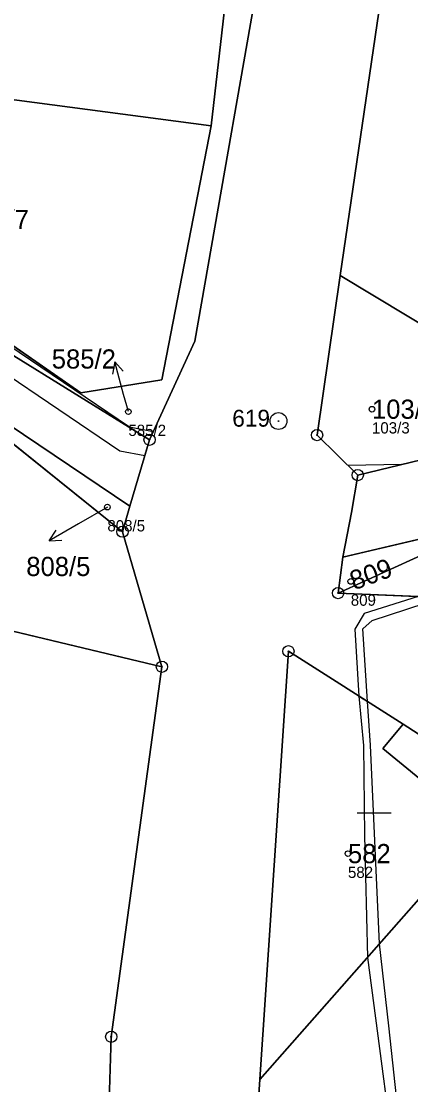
# Model space of a CAD drawing. Extents: x -734965 to -732523, y -1026217 to -1023680.
# Drawn here: x -734214.8 to -734180.3, y -1025552.4 to -1025458.1 of the extents above; entities that cross this region are included whole.
import ezdxf

# ---------------------------------------------------------------- set-up
doc = ezdxf.new("R2010")
doc.units = 0
for name, color, linetype in [('Vrstva 1', 7, 'Continuous'), ('Vrstva 13', 7, 'Continuous'), ('Vrstva 2', 7, 'Continuous'), ('Vrstva 3', 7, 'Continuous'), ('Vrstva 50', 7, 'Continuous'), ('Vrstva 51', 7, 'Continuous'), ('Vrstva 7', 7, 'Continuous'), ('Vrstva 8', 7, 'Continuous')]:
    doc.layers.add(name, color=color, linetype=linetype)

msp = doc.modelspace()

# ---------------------------------------------------------------- linework, layer by layer
at = {"layer": 'Vrstva 1'}
for p, q in [((-734196.71, -1025456.31), (-734198, -1025467.39)), ((-734209.55, -1025491.06), (-734254.45, -1025459.93)), ((-734254.45, -1025459.93), (-734198, -1025467.39)), ((-734198, -1025467.39), (-734202.38, -1025489.91)), ((-734165.69, -1025493.21), (-734186.54, -1025480.67)), ((-734205.86, -1025503.37), (-734226.72, -1025486.62)), ((-734226.72, -1025486.62), (-734205.2, -1025501.12)), ((-734202.38, -1025489.91), (-734209.55, -1025491.06)), ((-734203.46, -1025495.22), (-734205.2, -1025501.12)), ((-734205.2, -1025501.12), (-734205.86, -1025503.37)), ((-734172.72, -1025502.44), (-734186.74, -1025508.81)), ((-734172.72, -1025502.44), (-734186.32, -1025505.64)), ((-734202.36, -1025515.34), (-734205.86, -1025503.37)), ((-734186.74, -1025508.81), (-734186.32, -1025505.64)), ((-734235.25, -1025507.49), (-734202.36, -1025515.34)), ((-734176.27, -1025509.26), (-734186.74, -1025508.81)), ((-734180.96, -1025520.44), (-734179.64, -1025521.28)), ((-734174.08, -1025529.72), (-734193.69, -1025551.93)), ((-734195.13, -1025573.4), (-734193.69, -1025551.93))]:
    msp.add_line(p, q, dxfattribs=at)
for points in [[(-734186.54, -1025480.67), (-734181, -1025442.74), (-734169.15, -1025369.4), (-734156.59, -1025300)], [(-734195.46, -1025445.51), (-734192.73, -1025448.2), (-734199.45, -1025486.49), (-734203.46, -1025495.22)], [(-734263.8, -1025455.17), (-734222.99, -1025483.18), (-734203.46, -1025495.22)], [(-734186.54, -1025480.67), (-734188.6, -1025494.81), (-734184.99, -1025498.35)], [(-734184.99, -1025498.35), (-734166.17, -1025493.81), (-734165.12, -1025493.56)], [(-734186.32, -1025505.64), (-734185.56, -1025501.67), (-734184.99, -1025498.35)], [(-734193.69, -1025551.93), (-734191.14, -1025513.97), (-734180.96, -1025520.44)], [(-734202.36, -1025515.34), (-734206.86, -1025548.15), (-734208.37, -1025596.37), (-734208.2, -1025609.54), (-734207.24, -1025660.18), (-734210.4, -1025681.11), (-734230.12, -1025705.46), (-734245.49, -1025721.03)], [(-734180.96, -1025520.44), (-734182.76, -1025522.59), (-734174.08, -1025529.72)]]:
    msp.add_lwpolyline(points, dxfattribs=at)
at = {"layer": 'Vrstva 13'}
for points in [[(-734361.97, -1025583.56), (-734362.38, -1025583.9), (-734360.91, -1025585.58), (-734360.55, -1025585.27), (-734270.04, -1025510.33), (-734255.65, -1025499.06), (-734240.06, -1025486.22), (-734233.18, -1025477.89), (-734206.11, -1025496.21), (-734203.87, -1025496.63), (-734203.46, -1025495.22), (-734203.13, -1025494.51), (-734205.25, -1025494.11), (-734233.61, -1025474.92), (-734243.1, -1025486.41), (-734271.43, -1025508.6)], [(-734181.1, -1025497.41), (-734185.85, -1025497.51), (-734184.99, -1025498.35)], [(-734184.12, -1025518.43), (-734184.54, -1025511.99), (-734183.7, -1025511.25), (-734177.46, -1025509.21), (-734179.63, -1025509.12), (-734184.43, -1025510.63), (-734185.25, -1025512), (-734184.89, -1025517.94)], [(-734184.89, -1025517.94), (-734184.47, -1025522.34), (-734184.4, -1025530.29), (-734184.14, -1025541.11), (-734181.15, -1025563.75), (-734181.28, -1025567.46), (-734180.79, -1025570.32), (-734181.32, -1025574.41), (-734179.58, -1025577.99), (-734179.04, -1025577.73), (-734180.7, -1025574.31), (-734180.15, -1025570.52), (-734180.68, -1025567.42), (-734180.53, -1025563.04), (-734182.22, -1025547.18), (-734183.07, -1025539.91), (-734183.87, -1025522.3), (-734184.12, -1025518.43)]]:
    msp.add_lwpolyline(points, close=True, dxfattribs=at)
at = {"layer": 'Vrstva 3'}
msp.add_line((-734185.038, -1025528.3), (-734182.038, -1025528.3), dxfattribs=at)
at = {"layer": 'Vrstva 50'}
for centre in [(-734205.34, -1025492.73), (-734183.73, -1025492.51), (-734207.2, -1025501.19), (-734185.61, -1025507.78), (-734185.86, -1025531.91)]:
    msp.add_circle(centre, 0.25, dxfattribs=at)
at = {"layer": 'Vrstva 51'}
for points in [[(-734192.77, -1025655.13), (-734195.13, -1025573.4), (-734193.69, -1025551.93), (-734191.14, -1025513.97), (-734180.96, -1025520.44), (-734179.64, -1025521.28), (-734165.41, -1025504.9), (-734163.5, -1025502.7), (-734176.27, -1025509.26), (-734186.74, -1025508.81), (-734186.32, -1025505.64), (-734185.56, -1025501.67), (-734184.99, -1025498.35), (-734188.6, -1025494.81), (-734186.54, -1025480.67), (-734181, -1025442.74), (-734169.15, -1025369.4), (-734156.59, -1025300)], [(-734194.12, -1025358.97), (-734195.38, -1025379.43), (-734196.25, -1025388.44), (-734196.61, -1025399.41), (-734197.28, -1025419.42), (-734197.72, -1025429.14), (-734197.39, -1025432.52), (-734196.17, -1025444.81), (-734195.46, -1025445.51), (-734192.73, -1025448.2), (-734199.45, -1025486.49), (-734203.46, -1025495.22), (-734205.2, -1025501.12), (-734205.86, -1025503.37), (-734202.36, -1025515.34), (-734206.86, -1025548.15), (-734208.37, -1025596.37), (-734208.2, -1025609.54), (-734207.24, -1025660.18)], [(-734408.65, -1025376.56), (-734352.1, -1025403.23), (-734332.12, -1025413.11), (-734329.37, -1025414.87), (-734311.09, -1025424.35), (-734301.4, -1025430.8), (-734294.32, -1025437.04), (-734286.2, -1025442.28), (-734276.38, -1025449.51), (-734274.57, -1025450.96), (-734262.95, -1025459.45), (-734261.75, -1025460.33), (-734233.78, -1025481.1), (-734226.72, -1025486.62), (-734205.2, -1025501.12), (-734203.46, -1025495.22), (-734222.99, -1025483.18), (-734263.8, -1025455.17), (-734266.91, -1025452.06), (-734308.55, -1025423.43), (-734328.09, -1025410.59), (-734377.2, -1025388.12), (-734422.07, -1025368.4)], [(-734181, -1025442.74), (-734186.54, -1025480.67), (-734165.69, -1025493.21), (-734164.83, -1025492.89), (-734164.35, -1025493.02), (-734163.91, -1025492.8), (-734163.87, -1025492.31), (-734162.26, -1025491.06), (-734160.77, -1025489.7), (-734159.53, -1025488.12), (-734158.87, -1025486.23), (-734158.67, -1025484.23), (-734158.88, -1025482.22), (-734159.26, -1025480.77), (-734172.24, -1025442.54)], [(-734080.79, -1025492.01), (-734115.3, -1025489.58), (-734156.72, -1025495.18), (-734160.08, -1025496.7), (-734165.12, -1025493.56), (-734166.17, -1025493.81), (-734184.99, -1025498.35), (-734185.56, -1025501.67), (-734186.32, -1025505.64), (-734172.72, -1025502.44), (-734168.11, -1025501.36), (-734160.71, -1025499.62), (-734158.48, -1025499.09), (-734156.85, -1025498.71), (-734144.25, -1025495.75), (-734122.54, -1025492.68), (-734091.71, -1025493.39)]]:
    msp.add_lwpolyline(points, dxfattribs=at)
for points in [[(-734222.99, -1025483.18), (-734203.46, -1025495.22), (-734199.45, -1025486.49), (-734192.73, -1025448.2), (-734195.46, -1025445.51), (-734196.71, -1025456.31), (-734198, -1025467.39), (-734202.38, -1025489.91), (-734209.55, -1025491.06), (-734254.45, -1025459.93), (-734263.46, -1025453.25), (-734263.8, -1025455.17)], [(-734198, -1025467.39), (-734196.71, -1025456.31), (-734262.44, -1025447.52), (-734263.46, -1025453.25), (-734254.45, -1025459.93)], [(-734202.38, -1025489.91), (-734198, -1025467.39), (-734254.45, -1025459.93), (-734209.55, -1025491.06)], [(-734166.17, -1025493.81), (-734165.12, -1025493.56), (-734165.69, -1025493.21), (-734186.54, -1025480.67), (-734188.6, -1025494.81), (-734184.99, -1025498.35)], [(-734205.86, -1025503.37), (-734226.72, -1025486.62), (-734229.03, -1025488.91), (-734245.3, -1025505.09), (-734235.25, -1025507.49), (-734202.36, -1025515.34)], [(-734226.72, -1025486.62), (-734205.86, -1025503.37), (-734205.2, -1025501.12)], [(-734163.5, -1025502.7), (-734160.71, -1025499.62), (-734168.11, -1025501.36), (-734172.72, -1025502.44), (-734186.74, -1025508.81), (-734176.27, -1025509.26)], [(-734172.72, -1025502.44), (-734186.32, -1025505.64), (-734186.74, -1025508.81)], [(-734346.17, -1025601.95), (-734290.49, -1025668.19), (-734245.49, -1025721.03), (-734230.12, -1025705.46), (-734210.4, -1025681.11), (-734207.24, -1025660.18), (-734208.2, -1025609.54), (-734208.37, -1025596.37), (-734206.86, -1025548.15), (-734202.36, -1025515.34), (-734235.25, -1025507.49), (-734240.44, -1025516.98), (-734268.35, -1025539.41)], [(-734180.96, -1025520.44), (-734191.14, -1025513.97), (-734193.69, -1025551.93), (-734174.08, -1025529.72), (-734182.76, -1025522.59)], [(-734157.92, -1025601.02), (-734156.65, -1025601.83), (-734131.51, -1025560.59), (-734143.83, -1025550.67), (-734158.5, -1025538.55), (-734160.93, -1025536.54), (-734178.55, -1025522), (-734179.64, -1025521.28), (-734180.96, -1025520.44), (-734182.76, -1025522.59), (-734174.08, -1025529.72), (-734145.92, -1025552.87), (-734135.61, -1025561.34), (-734171.8, -1025620.71), (-734192.77, -1025655.13), (-734192.68, -1025658.27), (-734172.12, -1025624.41)], [(-734171.8, -1025620.71), (-734167.94, -1025576.06), (-734145.92, -1025552.87), (-734174.08, -1025529.72), (-734193.69, -1025551.93), (-734195.13, -1025573.4), (-734192.77, -1025655.13)]]:
    msp.add_lwpolyline(points, close=True, dxfattribs=at)
at = {"layer": 'Vrstva 7'}
for p, q in [((-734206.537, -1025488.301), (-734206.761, -1025489.398)), ((-734205.76, -1025491.2), (-734206.537, -1025488.301)), ((-734206.537, -1025488.301), (-734205.794, -1025489.139)), ((-734205.34, -1025492.73), (-734205.76, -1025491.2)), ((-734207.2, -1025501.19), (-734209.77, -1025502.68)), ((-734209.77, -1025502.68), (-734212.369, -1025504.18)), ((-734212.369, -1025504.18), (-734211.752, -1025503.246)), ((-734212.369, -1025504.18), (-734211.251, -1025504.113))]:
    msp.add_line(p, q, dxfattribs=at)
at = {"layer": 'Vrstva 8'}
for centre, radius in [((-734192.02, -1025493.56), 0.75), ((-734192.02, -1025493.56), 0.03), ((-734203.46, -1025495.22), 0.5), ((-734188.6, -1025494.81), 0.5), ((-734188.6, -1025494.81), 0.0303), ((-734203.46, -1025495.22), 0.0303), ((-734184.99, -1025498.35), 0.5), ((-734184.99, -1025498.35), 0.0303), ((-734205.86, -1025503.37), 0.5), ((-734205.86, -1025503.37), 0.0303), ((-734186.74, -1025508.81), 0.5), ((-734186.74, -1025508.81), 0.0303), ((-734191.14, -1025513.97), 0.5), ((-734191.14, -1025513.97), 0.0303), ((-734202.36, -1025515.34), 0.5), ((-734202.36, -1025515.34), 0.0303), ((-734206.86, -1025548.15), 0.5), ((-734206.86, -1025548.15), 0.0303)]:
    msp.add_circle(centre, radius, dxfattribs=at)

# ---------------------------------------------------------------- texts
at = {"layer": 'Vrstva 2'}
for s, p in [('585/7', (-734219.85, -1025476.549)), ('585/2', (-734212.136, -1025488.91)), ('103/3', (-734183.73, -1025493.36)), ('808/5', (-734214.396, -1025507.303)), ('582', (-734185.86, -1025532.76))]:
    msp.add_text(s, height=1.7, dxfattribs=at).set_placement(p)
msp.add_text('809', height=1.7, rotation=20, dxfattribs=at).set_placement((-734185.319, -1025508.578))
at = {"layer": 'Vrstva 50'}
for s, p in [('585/2', (-734205.34, -1025494.886)), ('103/3', (-734183.73, -1025494.666)), ('808/5', (-734207.2, -1025503.346)), ('809', (-734185.61, -1025509.936)), ('582', (-734185.86, -1025534.066))]:
    msp.add_text(s, height=1, dxfattribs=at).set_placement(p)
at = {"layer": 'Vrstva 8'}
msp.add_text('619', height=1.5, dxfattribs=at).set_placement((-734196.123, -1025494.06))

doc.saveas('drawing.dxf')
